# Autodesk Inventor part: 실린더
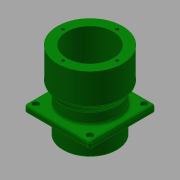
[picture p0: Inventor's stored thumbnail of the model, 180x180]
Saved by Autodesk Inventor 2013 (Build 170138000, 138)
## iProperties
Created: 2016-11
Part Number: 실린더
Material: 일반
Document SubType Name: Modeling
Designer: mduedu
Density: 2.71 g/cm^3
Mass: 592.083 g
Surface Area: 591.531 cm^2
Volume: 218.481 cm^3
Author: mduedu
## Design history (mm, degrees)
sketch "스케치1"
  geometry: L1 (0, 0)-(0, 101); L2 (30, 0)-(30, 101); L3 (30, 101)-(42, 101); L4 (42, 101)-(42, 61); L5 (42, 61)-(35, 51); L6 (35, 51)-(35, 0); L7 (35, 0)-(30, 0)
  constraints: 14 end point, 4 parallel, 2 horizontal alignment, 1 perpendicular, 1 vertical
  dimensions: "d0" = 101 distance of L1.start L1.end; "d1" = 60 diameter of L2.end L1; "d2" = 84 diameter of L3.end L1; "d3" = 70 diameter of L6.end L1; "d4" = 40 distance of L3.end L4.end; "d5" = 50 vertical distance of L5.end L3.end
revolve "회전1" sketch "스케치1" stored, may be unused: angle "d6" = 90 deg
node "작업 평면1"
sketch "스케치2"
  geometry: L1 (-42.5, -42.5)-(42.5, -42.5); L2 (42.5, -42.5)-(42.5, 42.5); L3 (42.5, 42.5)-(-42.5, 42.5); L4 (-42.5, 42.5)-(-42.5, -42.5); L5 (-42.5, -42.5)-(42.5, 42.5); L6 (42.5, -42.5)-(-42.5, 42.5); C1 r 35 at (0, 0) reference; C2 r 35 at (0, 0); 1 further point
  constraints: 12 end point, 2 midpoint, 2 parallel, 2 perpendicular, 1 centre point, 1 coincident, 1 concentric, 1 horizontal
  dimensions: "d8" = 85 distance of L2.end L3.end
extrude "돌출1" join sketch "스케치2" distance "d10" = 8; taper "d11" = 0 deg
fillet "모깎기1" dims "d12" = 3
fillet "모깎기2" dims "d13" = 3
chamfer "모따기1" distance "d14" = 1; stored, may be unused: second distance "d15" = 2, angle "d16" = 45 deg
chamfer "모따기2" distance "d17" = 5; stored, may be unused: second distance "d18" = 2, angle "d19" = 15 deg
sketch "스케치3"
  geometry: L1 (-35, -35)-(35, -35); L2 (35, -35)-(35, 35); L3 (35, 35)-(-35, 35); L4 (-35, 35)-(-35, -35); L5 (-35, -35)-(35, 35); L6 (35, -35)-(-35, 35); 5 further points
  constraints: 12 end point, 4 coincident, 2 midpoint, 2 parallel, 1 horizontal, 1 perpendicular
  dimensions: "d20" = 70 distance of L3.end L2.end; "d21" = 70 distance of L2.end L1.end
sketch "스케치4"
  geometry: 4 further points
  constraints: 4 other
hole "구멍1" sketch "스케치4" at (-35, 35), (35, 35), (35, -35), (-35, -35) diameter "d22" = 4.5; stored, may be unused: countersink angle "d26" = 90 deg, drill point angle "d28" = 0 deg; dims "d23" = 6, "d24" = 8, "d25" = 4.6, "d27" = 8
sketch "스케치5"
  geometry: 4 further points
  constraints: 4 other
hole "구멍2" sketch "스케치5" at (0, -35), (35, 0), (-35, 0), (0, 35) diameter "d29" = 4.134; stored, may be unused: countersink angle "d33" = 90 deg, drill point angle "d35" = 120 deg; dims "d30" = 7.5, "d31" = 4, "d32" = 2, "d34" = 10
node "솔리드1"
other parameters: "d7" = -27
